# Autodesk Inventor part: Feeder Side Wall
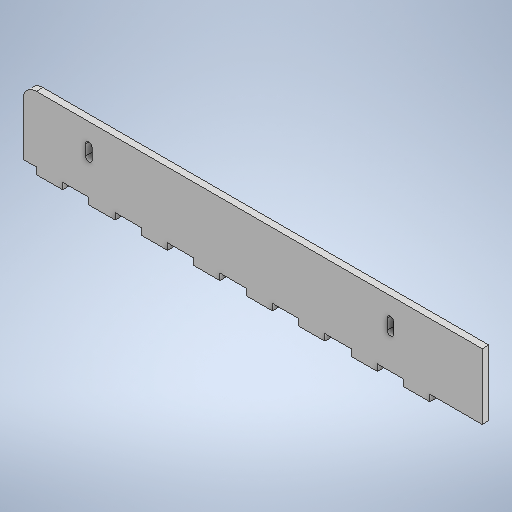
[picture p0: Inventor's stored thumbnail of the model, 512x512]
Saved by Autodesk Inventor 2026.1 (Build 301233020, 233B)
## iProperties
Created: 2026-11
Part Number: Feeder Side Wall
Material: Generic
Document SubType Name: Modeling
Designer: hp
Density: 1 g/cm^3
Appearance: Default
Author: hp
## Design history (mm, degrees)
sketch "Sketch1"
  geometry: L1 (0, 0)-(350, 0); L2 (350, 0)-(350, 50); L3 (350, 50)-(0, 50); L4 (0, 50)-(0, 0); L5 (0, 0)-(350, 0); L6 (350, 0)-(350, -5); L7 (350, -5)-(0, -5); L8 (0, -5)-(0, 0); 1 further point
  constraints: 16 end point, 4 parallel, 2 horizontal, 2 perpendicular
  dimensions: "d0" = 350 distance of L3.end L2.end; "d1" = 50 distance of L2.end L1.end; "d40" = 5 distance of L5.end L6.end; "d50" = 350 distance of L6.end L7.end (= d0)
extrude "Extrusion1" new body sketch "Sketch1" distance "d2" = 5; taper "d3" = 0 deg
fillet "Fillet2" dims "d33" = 10
sketch "Sketch7"
  geometry: L1 (0, -5)-(330, -5) reference; L2 (0, 0)-(350, 0) reference; L3 (0, -5)-(0, 0) reference; L4 (10, 0)-(30, 0); L5 (30, 0)-(30, -5); L6 (30, -5)-(10, -5); L7 (10, -5)-(10, 0); L8 (50, 0)-(70, 0); L9 (70, 0)-(70, -5); L10 (70, -5)-(50, -5); L11 (50, -5)-(50, 0); L12 (90, 0)-(110, 0); L13 (110, 0)-(110, -5); L14 (110, -5)-(90, -5); L15 (90, -5)-(90, 0); L16 (130, 0)-(150, 0); L17 (150, 0)-(150, -5); L18 (150, -5)-(130, -5); L19 (130, -5)-(130, 0); L20 (170, 0)-(190, 0); L21 (190, 0)-(190, -5); L22 (190, -5)-(170, -5); L23 (170, -5)-(170, 0); L24 (210, 0)-(230, 0); L25 (230, 0)-(230, -5); L26 (230, -5)-(210, -5); L27 (210, -5)-(210, 0); L28 (250, 0)-(270, 0); L29 (270, 0)-(270, -5); L30 (270, -5)-(250, -5); L31 (250, -5)-(250, 0); L32 (290, 0)-(310, 0); L33 (310, 0)-(310, -5); L34 (310, -5)-(290, -5); L35 (290, -5)-(290, 0); 6 further points; 1 other entity
  constraints: 64 end point, 2 horizontal, 2 parallel, 1 perpendicular, 1 point on line, 58 other
  dimensions: "d51" = 20 distance of L5.end L6.end; "d52" = 10 distance between parallel lines of L3 L7; "d66" = 40 distance of L4.start L8.start
extrude "Extrusion3" join sketch "Sketch7" distance "d62" = 5; taper "d63" = 0 deg
sketch "Sketch8"
  geometry: L1 (0, 40)-(0, 0) reference; L2 (0, 0)-(10, 0) reference; L3 (10, 0)-(10, -5) reference; L4 (10, -5)-(30, -5) reference; L5 (30, -5)-(30, 0) reference; L6 (30, 0)-(50, 0) reference; L7 (50, 0)-(50, -5) reference; L8 (50, -5)-(70, -5) reference; L9 (70, -5)-(70, 0) reference; L10 (70, 0)-(90, 0) reference; L11 (90, 0)-(90, -5) reference; L12 (90, -5)-(110, -5) reference; L13 (110, -5)-(110, 0) reference; L14 (110, 0)-(130, 0) reference; L15 (130, 0)-(130, -5) reference; L16 (130, -5)-(150, -5) reference; L17 (150, -5)-(150, 0) reference; L18 (150, 0)-(170, 0) reference; L19 (170, 0)-(170, -5) reference; L20 (170, -5)-(190, -5) reference; L21 (190, -5)-(190, 0) reference; L22 (190, 0)-(210, 0) reference; L23 (210, 0)-(210, -5) reference; L24 (210, -5)-(230, -5) reference; L25 (230, -5)-(230, 0) reference; L26 (230, 0)-(250, 0) reference; L27 (250, 0)-(250, -5) reference; L28 (250, -5)-(270, -5) reference; L29 (270, -5)-(270, 0) reference; L30 (270, 0)-(290, 0) reference; L31 (290, 0)-(290, -5) reference; L32 (290, -5)-(310, -5) reference; L33 (310, -5)-(310, 0) reference; L34 (310, 0)-(350, 0) reference; L35 (350, 0)-(350, 50) reference; L36 (350, 50)-(10, 50) reference; L37 (50, 26)-(50, 34); L38 (52.5, 26)-(52.5, 34); L39 (47.5, 34)-(47.5, 26); L40 (282.5, 26)-(282.5, 34); L41 (280, 26)-(280, 34); L42 (277.5, 34)-(277.5, 26); A1 r 10 centre (10, 40) between (10, 50) and (0, 40) reference; A2 r 2.5 centre (50, 26) between (47.5, 26) and (52.5, 26); A3 r 2.5 centre (50, 34) between (52.5, 34) and (47.5, 34); A4 r 2.5 centre (280, 26) between (277.5, 26) and (282.5, 26); A5 r 2.5 centre (280, 34) between (282.5, 34) and (277.5, 34); 3 further points
  constraints: 16 end point, 8 point on circle, 8 tangent, 4 centre point, 2 midpoint, 2 parallel, 2 vertical
  dimensions: "d71" = 5 diameter of A3; "d72" = 30 distance from line of L6 point (50, 30); "d73" = 50 distance from line of L1 point (50, 30); "d74" = 4 distance of point (50, 30) L37.end; "d75" = 5 diameter of A5; "d76" = 4 distance of point (280, 30) L41.end; "d77" = 30 distance from line of L10 point (280, 30); "d81" = 230 distance of point (50, 30) point (280, 30)
extrude "Extrusion4" cut sketch "Sketch8" stored distance "d79" = 10; taper "d80" = 0 deg
body "Solid1"
node "Sketch Rectangular Pattern3" dims "d66" = 40, "d69" = 10
node "Projected Loop1"
